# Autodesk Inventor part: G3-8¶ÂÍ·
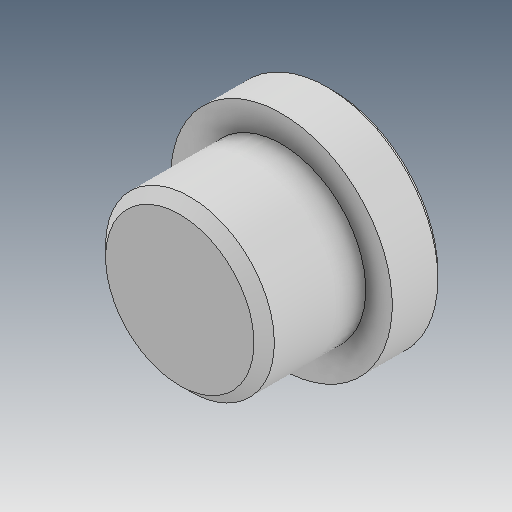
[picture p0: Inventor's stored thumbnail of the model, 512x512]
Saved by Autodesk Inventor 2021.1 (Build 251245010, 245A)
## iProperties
Created: 2019-05
Part Number: G3-8¶ÂÍ·
Material: Ogólny
Document SubType Name: Modeling
Designer: user
Density: 1 g/cm^3
Appearance: Domyślna
Author: user
Revision Number: ÈÎºÎ
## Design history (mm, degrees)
feature "ÊäÈë1"
node "Bryła1"
